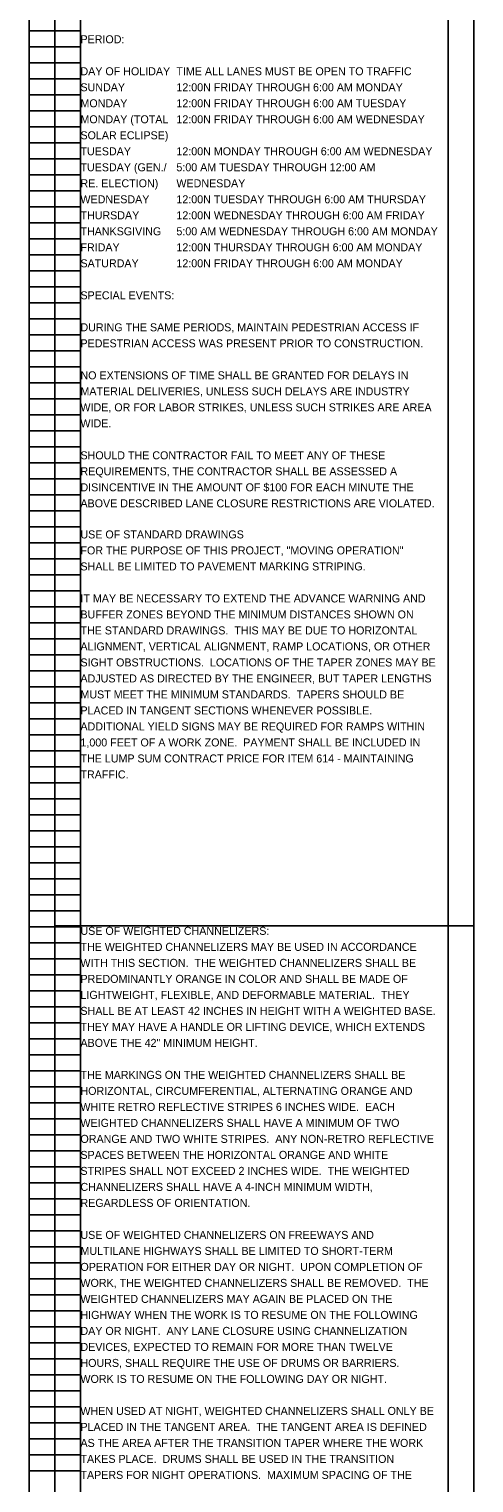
# Model space of a CAD drawing. Extents: x 0 to 19, y -301 to 22.
# Drawn here: x 1.5 to 9.29, y -28.91 to -3.47 of the extents above; entities that cross this region are included whole.
import ezdxf

# ---------------------------------------------------------------- set-up
doc = ezdxf.new("R2010")
doc.units = 0
doc.layers.add('SC_Scratch1', color=7, linetype='Continuous')
doc.layers.add('SH_Text', color=7, linetype='Continuous')

msp = doc.modelspace()

# ---------------------------------------------------------------- linework, layer by layer
at = {"layer": 'SC_Scratch1'}
for p, q in [((1.5, -19.18), (1.5, 0.98)), ((2.4, -19.18), (2.4, 0.98)), ((8.84, -19.18), (8.84, 0.98)), ((1.5, -3.5), (2.4, -3.5)), ((1.5, -3.78), (2.4, -3.78)), ((1.5, -4.06), (2.4, -4.06)), ((1.5, -4.34), (2.4, -4.34)), ((1.5, -4.62), (2.4, -4.62)), ((1.5, -4.9), (2.4, -4.9)), ((1.5, -5.18), (2.4, -5.18)), ((1.5, -5.46), (2.4, -5.46)), ((1.5, -5.74), (2.4, -5.74)), ((1.5, -6.02), (2.4, -6.02)), ((1.5, -6.3), (2.4, -6.3)), ((1.5, -6.58), (2.4, -6.58)), ((1.5, -6.86), (2.4, -6.86)), ((1.5, -7.14), (2.4, -7.14)), ((1.5, -7.42), (2.4, -7.42)), ((1.5, -7.7), (2.4, -7.7)), ((1.5, -7.98), (2.4, -7.98)), ((1.5, -8.26), (2.4, -8.26)), ((1.5, -8.54), (2.4, -8.54)), ((1.5, -8.82), (2.4, -8.82)), ((1.5, -9.1), (2.4, -9.1)), ((1.5, -9.38), (2.4, -9.38)), ((1.5, -9.66), (2.4, -9.66)), ((1.5, -9.94), (2.4, -9.94)), ((1.5, -10.22), (2.4, -10.22)), ((1.5, -10.5), (2.4, -10.5)), ((1.5, -10.78), (2.4, -10.78)), ((1.5, -11.06), (2.4, -11.06)), ((1.5, -11.34), (2.4, -11.34)), ((1.5, -11.62), (2.4, -11.62)), ((1.5, -11.9), (2.4, -11.9)), ((1.5, -12.18), (2.4, -12.18)), ((1.5, -12.46), (2.4, -12.46)), ((1.5, -12.74), (2.4, -12.74)), ((1.5, -13.02), (2.4, -13.02)), ((1.5, -13.3), (2.4, -13.3)), ((1.5, -13.58), (2.4, -13.58)), ((1.5, -13.86), (2.4, -13.86)), ((1.5, -14.14), (2.4, -14.14)), ((1.5, -14.42), (2.4, -14.42)), ((1.5, -14.7), (2.4, -14.7)), ((1.5, -14.98), (2.4, -14.98)), ((1.5, -15.26), (2.4, -15.26)), ((1.5, -15.54), (2.4, -15.54)), ((1.5, -15.82), (2.4, -15.82)), ((1.5, -16.1), (2.4, -16.1)), ((1.5, -16.38), (2.4, -16.38)), ((1.5, -16.66), (2.4, -16.66)), ((1.5, -16.94), (2.4, -16.94)), ((1.5, -17.22), (2.4, -17.22)), ((1.5, -17.5), (2.4, -17.5)), ((1.5, -17.78), (2.4, -17.78)), ((1.5, -18.06), (2.4, -18.06)), ((1.5, -18.34), (2.4, -18.34)), ((1.5, -18.62), (2.4, -18.62)), ((1.5, -18.9), (2.4, -18.9)), ((1.5, -19.18), (2.4, -19.18)), ((1.5, -19.18), (2.4, -19.18)), ((1.5, -39.34), (1.5, -19.18)), ((2.4, -39.34), (2.4, -19.18)), ((8.84, -39.34), (8.84, -19.18)), ((1.5, -19.46), (2.4, -19.46)), ((1.5, -19.74), (2.4, -19.74)), ((1.5, -20.02), (2.4, -20.02)), ((1.5, -20.3), (2.4, -20.3)), ((1.5, -20.58), (2.4, -20.58)), ((1.5, -20.86), (2.4, -20.86)), ((1.5, -21.14), (2.4, -21.14)), ((1.5, -21.42), (2.4, -21.42)), ((1.5, -21.7), (2.4, -21.7)), ((1.5, -21.98), (2.4, -21.98)), ((1.5, -22.26), (2.4, -22.26)), ((1.5, -22.54), (2.4, -22.54)), ((1.5, -22.82), (2.4, -22.82)), ((1.5, -23.1), (2.4, -23.1)), ((1.5, -23.38), (2.4, -23.38)), ((1.5, -23.66), (2.4, -23.66)), ((1.5, -23.94), (2.4, -23.94)), ((1.5, -24.22), (2.4, -24.22)), ((1.5, -24.5), (2.4, -24.5)), ((1.5, -24.78), (2.4, -24.78)), ((1.5, -25.06), (2.4, -25.06)), ((1.5, -25.34), (2.4, -25.34)), ((1.5, -25.62), (2.4, -25.62)), ((1.5, -25.9), (2.4, -25.9)), ((1.5, -26.18), (2.4, -26.18)), ((1.5, -26.46), (2.4, -26.46)), ((1.5, -26.74), (2.4, -26.74)), ((1.5, -27.02), (2.4, -27.02)), ((1.5, -27.3), (2.4, -27.3)), ((1.5, -27.58), (2.4, -27.58)), ((1.5, -27.86), (2.4, -27.86)), ((1.5, -28.14), (2.4, -28.14)), ((1.5, -28.42), (2.4, -28.42)), ((1.5, -28.7), (2.4, -28.7))]:
    msp.add_line(p, q, dxfattribs=at)
for points in [[(1.95, 0.997), (9.29, 0.997), (9.29, -19.163), (1.95, -19.163)], [(1.95, -19.163), (9.29, -19.163), (9.29, -39.323), (1.95, -39.323)]]:
    msp.add_lwpolyline(points, close=True, dxfattribs=at)

# ---------------------------------------------------------------- texts
at = {"layer": 'SH_Text'}
for s, p in [('PERIOD:', (2.4, -3.719)), ('DAY OF HOLIDAY', (2.4, -4.279)), ('TIME ALL LANES MUST BE OPEN TO TRAFFIC', (4.08, -4.279)), ('SUNDAY', (2.4, -4.559)), ('12:00N FRIDAY THROUGH 6:00 AM MONDAY', (4.08, -4.559)), ('MONDAY', (2.4, -4.839)), ('12:00N FRIDAY THROUGH 6:00 AM TUESDAY', (4.08, -4.839)), ('MONDAY (TOTAL', (2.4, -5.119)), ('12:00N FRIDAY THROUGH 6:00 AM WEDNESDAY', (4.08, -5.119)), ('SOLAR ECLIPSE)', (2.4, -5.399)), ('TUESDAY', (2.4, -5.679)), ('12:00N MONDAY THROUGH 6:00 AM WEDNESDAY', (4.08, -5.679)), ('TUESDAY (GEN./', (2.4, -5.959)), ('5:00 AM TUESDAY THROUGH 12:00 AM ', (4.08, -5.959)), ('RE. ELECTION)', (2.4, -6.239)), ('WEDNESDAY', (4.08, -6.239)), ('WEDNESDAY', (2.4, -6.519)), ('12:00N TUESDAY THROUGH 6:00 AM THURSDAY', (4.08, -6.519)), ('THURSDAY', (2.4, -6.799)), ('12:00N WEDNESDAY THROUGH 6:00 AM FRIDAY', (4.08, -6.799)), ('THANKSGIVING', (2.4, -7.079)), ('5:00 AM WEDNESDAY THROUGH 6:00 AM MONDAY', (4.08, -7.079)), ('FRIDAY', (2.4, -7.359)), ('12:00N THURSDAY THROUGH 6:00 AM MONDAY', (4.08, -7.359)), ('SATURDAY', (2.4, -7.639)), ('12:00N FRIDAY THROUGH 6:00 AM MONDAY', (4.08, -7.639)), ('SPECIAL EVENTS:', (2.4, -8.199)), ('DURING THE SAME PERIODS, MAINTAIN PEDESTRIAN ACCESS IF ', (2.4, -8.759)), ('PEDESTRIAN ACCESS WAS PRESENT PRIOR TO CONSTRUCTION.', (2.4, -9.039)), ('NO EXTENSIONS OF TIME SHALL BE GRANTED FOR DELAYS IN ', (2.4, -9.599)), ('MATERIAL DELIVERIES, UNLESS SUCH DELAYS ARE INDUSTRY ', (2.4, -9.879)), ('WIDE, OR FOR LABOR STRIKES, UNLESS SUCH STRIKES ARE AREA ', (2.4, -10.159)), ('WIDE.', (2.4, -10.439)), ('SHOULD THE CONTRACTOR FAIL TO MEET ANY OF THESE ', (2.4, -10.999)), ('REQUIREMENTS, THE CONTRACTOR SHALL BE ASSESSED A ', (2.4, -11.279)), ('DISINCENTIVE IN THE AMOUNT OF $100 FOR EACH MINUTE THE ', (2.4, -11.559)), ('ABOVE DESCRIBED LANE CLOSURE RESTRICTIONS ARE VIOLATED.', (2.4, -11.839)), ('USE OF STANDARD DRAWINGS', (2.4, -12.383)), ('FOR THE PURPOSE OF THIS PROJECT, "MOVING OPERATION" ', (2.4, -12.663)), ('SHALL BE LIMITED TO PAVEMENT MARKING STRIPING.', (2.4, -12.943)), ('IT MAY BE NECESSARY TO EXTEND THE ADVANCE WARNING AND ', (2.4, -13.503)), ('BUFFER ZONES BEYOND THE MINIMUM DISTANCES SHOWN ON ', (2.4, -13.783)), ('THE STANDARD DRAWINGS.  THIS MAY BE DUE TO HORIZONTAL ', (2.4, -14.063)), ('ALIGNMENT, VERTICAL ALIGNMENT, RAMP LOCATIONS, OR OTHER ', (2.4, -14.343)), ('SIGHT OBSTRUCTIONS.  LOCATIONS OF THE TAPER ZONES MAY BE ', (2.4, -14.623)), ('ADJUSTED AS DIRECTED BY THE ENGINEER, BUT TAPER LENGTHS ', (2.4, -14.903)), ('MUST MEET THE MINIMUM STANDARDS.  TAPERS SHOULD BE ', (2.4, -15.183)), ('PLACED IN TANGENT SECTIONS WHENEVER POSSIBLE.  ', (2.4, -15.463)), ('ADDITIONAL YIELD SIGNS MAY BE REQUIRED FOR RAMPS WITHIN ', (2.4, -15.743)), ('1,000 FEET OF A WORK ZONE.  PAYMENT SHALL BE INCLUDED IN ', (2.4, -16.023)), ('THE LUMP SUM CONTRACT PRICE FOR ITEM 614 - MAINTAINING ', (2.4, -16.303)), ('TRAFFIC.', (2.4, -16.583)), ('USE OF WEIGHTED CHANNELIZERS:', (2.4, -19.32)), ('THE WEIGHTED CHANNELIZERS MAY BE USED IN ACCORDANCE ', (2.4, -19.6)), ('WITH THIS SECTION.  THE WEIGHTED CHANNELIZERS SHALL BE ', (2.4, -19.88)), ('PREDOMINANTLY ORANGE IN COLOR AND SHALL BE MADE OF ', (2.4, -20.16)), ('LIGHTWEIGHT, FLEXIBLE, AND DEFORMABLE MATERIAL.  THEY ', (2.4, -20.44)), ('SHALL BE AT LEAST 42 INCHES IN HEIGHT WITH A WEIGHTED BASE.  ', (2.4, -20.72)), ('THEY MAY HAVE A HANDLE OR LIFTING DEVICE, WHICH EXTENDS ', (2.4, -21)), ('ABOVE THE 42" MINIMUM HEIGHT.', (2.4, -21.28)), ('THE MARKINGS ON THE WEIGHTED CHANNELIZERS SHALL BE ', (2.4, -21.84)), ('HORIZONTAL, CIRCUMFERENTIAL, ALTERNATING ORANGE AND ', (2.4, -22.12)), ('WHITE RETRO REFLECTIVE STRIPES 6 INCHES WIDE.  EACH ', (2.4, -22.4)), ('WEIGHTED CHANNELIZERS SHALL HAVE A MINIMUM OF TWO ', (2.4, -22.68)), ('ORANGE AND TWO WHITE STRIPES.  ANY NON-RETRO REFLECTIVE ', (2.4, -22.96)), ('SPACES BETWEEN THE HORIZONTAL ORANGE AND WHITE ', (2.4, -23.24)), ('STRIPES SHALL NOT EXCEED 2 INCHES WIDE.  THE WEIGHTED ', (2.4, -23.52)), ('CHANNELIZERS SHALL HAVE A 4-INCH MINIMUM WIDTH, ', (2.4, -23.8)), ('REGARDLESS OF ORIENTATION.', (2.4, -24.08)), ('USE OF WEIGHTED CHANNELIZERS ON FREEWAYS AND ', (2.4, -24.64)), ('MULTILANE HIGHWAYS SHALL BE LIMITED TO SHORT-TERM ', (2.4, -24.92)), ('OPERATION FOR EITHER DAY OR NIGHT.  UPON COMPLETION OF ', (2.4, -25.2)), ('WORK, THE WEIGHTED CHANNELIZERS SHALL BE REMOVED.  THE ', (2.4, -25.48)), ('WEIGHTED CHANNELIZERS MAY AGAIN BE PLACED ON THE ', (2.4, -25.76)), ('HIGHWAY WHEN THE WORK IS TO RESUME ON THE FOLLOWING ', (2.4, -26.04)), ('DAY OR NIGHT.  ANY LANE CLOSURE USING CHANNELIZATION ', (2.4, -26.32)), ('DEVICES, EXPECTED TO REMAIN FOR MORE THAN TWELVE ', (2.4, -26.6)), ('HOURS, SHALL REQUIRE THE USE OF DRUMS OR BARRIERS.  ', (2.4, -26.88)), ('WORK IS TO RESUME ON THE FOLLOWING DAY OR NIGHT.', (2.4, -27.16)), ('WHEN USED AT NIGHT, WEIGHTED CHANNELIZERS SHALL ONLY BE ', (2.4, -27.72)), ('PLACED IN THE TANGENT AREA.  THE TANGENT AREA IS DEFINED ', (2.4, -28)), ('AS THE AREA AFTER THE TRANSITION TAPER WHERE THE WORK ', (2.4, -28.28)), ('TAKES PLACE.  DRUMS SHALL BE USED IN THE TRANSITION ', (2.4, -28.56)), ('TAPERS FOR NIGHT OPERATIONS.  MAXIMUM SPACING OF THE ', (2.4, -28.84))]:
    msp.add_text(s, height=0.14, dxfattribs=at).set_placement(p)

doc.saveas('drawing.dxf')
